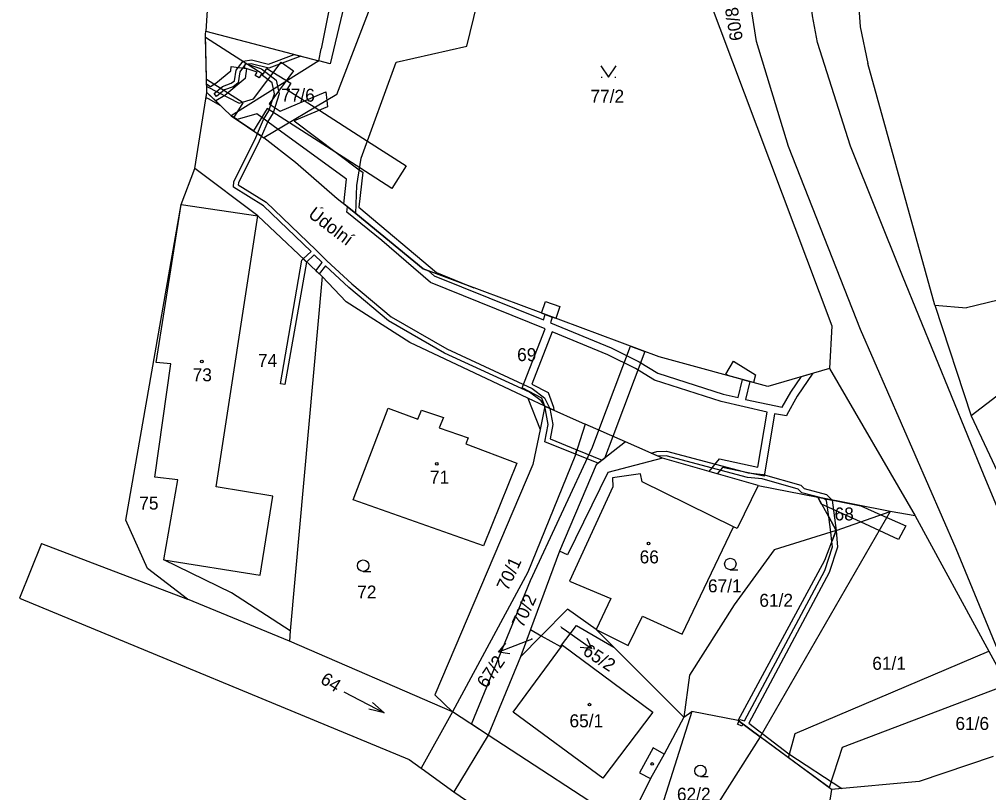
# Model space of a CAD drawing. Extents: x -670359 to -668019, y -978807 to -976674.
# Drawn here: x -670358.7 to -670231.4, y -977812.9 to -977711.4 of the extents above; entities that cross this region are included whole.
import ezdxf

# ---------------------------------------------------------------- set-up
doc = ezdxf.new("R2010")
doc.units = 0
for name, color, linetype in [('Hranice kat_území', 7, 'Continuous'), ('Hranice parcel', 7, 'Continuous'), ('Parcelní čísla', 7, 'Continuous'), ('Pop  PČ popisy', 7, 'Continuous'), ('Vnitřní kresba', 7, 'Continuous'), ('Věcná břemena k části', 7, 'Continuous'), ('Značky budov', 7, 'Continuous'), ('Značky kultur', 7, 'Continuous')]:
    doc.layers.add(name, color=color, linetype=linetype)

msp = doc.modelspace()

# ---------------------------------------------------------------- linework, layer by layer
at = {"layer": 'Hranice kat_území'}
for points in [[(-670332.34, -977684.03), (-670334.21, -977712.94)], [(-670334.24, -977713.37), (-670334.21, -977712.94)], [(-670334.05, -977720.97), (-670334.24, -977713.37)], [(-670335.64, -977730.96), (-670334.05, -977720.97)], [(-670337.44, -977735.66), (-670335.64, -977730.96)], [(-670344.7, -977777.12), (-670337.44, -977735.66)], [(-670341.86, -977783.46), (-670344.7, -977777.12)], [(-670355.76, -977780.18), (-670358.68, -977787.38)], [(-670355.76, -977780.18), (-670336.61, -977787.5)], [(-670336.61, -977787.5), (-670341.86, -977783.46)], [(-670358.68, -977787.38), (-670307.5, -977808.55)], [(-670307.5, -977808.55), (-670305.92, -977809.69)], [(-670305.92, -977809.69), (-670305.49, -977810)], [(-670305.49, -977810), (-670301.94, -977812.57)], [(-670301.94, -977812.57), (-670301.61, -977812.81)], [(-670301.61, -977812.81), (-670283.75, -977825.01)]]:
    msp.add_lwpolyline(points, dxfattribs=at)
at = {"layer": 'Hranice parcel'}
for points in [[(-670228.39, -977798.54), (-670235.68, -977780.88), (-670248.21, -977752.09), (-670257.66, -977728.06), (-670261.88, -977714.27), (-670262.87, -977707.81), (-670263.3, -977700.83), (-670262.9, -977694.87), (-670261.36, -977686.41), (-670250.36, -977641.2)], [(-670183.39, -977889.81), (-670193.56, -977862.25), (-670201.26, -977845.22), (-670205.62, -977834.5), (-670231.98, -977771.32), (-670242.71, -977745.05), (-670249.53, -977728.04), (-670253.85, -977714.41), (-670254.54, -977710.9), (-670255.07, -977705.75), (-670255.17, -977699.87), (-670254.7, -977694.67), (-670252.82, -977684.15), (-670242.83, -977643.13)], [(-670306.8, -977670.72), (-670317.87, -977717.22)], [(-670299.92, -977714.89), (-670294.49, -977692.62)], [(-670248.85, -977704.32), (-670248.28, -977712.37)], [(-670317.01, -977721.25), (-670311.54, -977706.97)], [(-670268.34, -977708.07), (-670252.01, -977751.62)], [(-670334.21, -977712.94), (-670319.36, -977716.83)], [(-670248.28, -977712.37), (-670247.28, -977717.18)], [(-670309.21, -977716.99), (-670299.92, -977714.89)], [(-670317.87, -977717.22), (-670319.36, -977716.83)], [(-670313.79, -977729.59), (-670309.21, -977716.99)], [(-670238.46, -977748.91), (-670247.28, -977717.18)], [(-670330.87, -977724.03), (-670334.05, -977720.97)], [(-670317.01, -977721.25), (-670326.57, -977726.94)], [(-670330.87, -977724.03), (-670326.57, -977726.94)], [(-670322.43, -977730.17), (-670326.57, -977726.94)], [(-670314.37, -977733.19), (-670313.79, -977729.59)], [(-670327.36, -977737.17), (-670335.64, -977730.96)], [(-670316.95, -977734.93), (-670322.43, -977730.17)], [(-670314.48, -977736.86), (-670314.37, -977733.19)], [(-670314.48, -977736.86), (-670316.95, -977734.93)], [(-670340.71, -977756.44), (-670337.44, -977735.66)], [(-670332.82, -977772.73), (-670327.36, -977737.17)], [(-670318.94, -977745.15), (-670327.36, -977737.17)], [(-670305.65, -977744.12), (-670314.48, -977736.86)], [(-670318.94, -977745.15), (-670323.11, -977791.67)], [(-670315.76, -977748.45), (-670318.94, -977745.15)], [(-670274.68, -977755.7), (-670305.65, -977744.12)], [(-670227.25, -977747.55), (-670234.3, -977749.26)], [(-670307.4, -977753.79), (-670315.76, -977748.45)], [(-670238.46, -977748.91), (-670233.69, -977763.42)], [(-670238.46, -977748.91), (-670234.3, -977749.26)], [(-670252.01, -977751.62), (-670252.29, -977757.21)], [(-670291.93, -977761.1), (-670307.4, -977753.79)], [(-670220.97, -977753.67), (-670233.69, -977763.42)], [(-670340.89, -977771.47), (-670338.79, -977756.61)], [(-670338.79, -977756.61), (-670340.71, -977756.44)], [(-670260.39, -977759.56), (-670274.68, -977755.7)], [(-670252.29, -977757.21), (-670260.39, -977759.56)], [(-670252.29, -977757.21), (-670241.06, -977776.57)], [(-670289.68, -977762.16), (-670291.93, -977761.1)], [(-670314.83, -977774.45), (-670310.26, -977762.41)], [(-670310.26, -977762.41), (-670306.35, -977763.87)], [(-670306.35, -977763.87), (-670305.86, -977762.68)], [(-670305.86, -977762.68), (-670302.99, -977763.66)], [(-670289.68, -977762.16), (-670290.31, -977765.22)], [(-670289.68, -977762.16), (-670284.38, -977764.51)], [(-670302.99, -977763.66), (-670303.56, -977765.01)], [(-670233.69, -977763.42), (-670224.46, -977783.08)], [(-670303.56, -977765.01), (-670299.73, -977766.32)], [(-670290.31, -977765.22), (-670291.27, -977769.82)], [(-670284.38, -977764.51), (-670285.74, -977768.77)], [(-670279.08, -977766.86), (-670284.38, -977764.51)], [(-670299.73, -977766.32), (-670300.05, -977767.12)], [(-670279.08, -977766.86), (-670282.95, -977769.88)], [(-670274.22, -977768.98), (-670279.08, -977766.86)], [(-670300.05, -977767.12), (-670293.35, -977769.64)], [(-670285.74, -977768.77), (-670291.91, -977783.94)], [(-670261.68, -977772.58), (-670274.22, -977768.98)], [(-670291.27, -977769.82), (-670304.13, -977800.04)], [(-670293.35, -977769.64), (-670297.75, -977780.49)], [(-670282.95, -977769.88), (-670287.75, -977781.2)], [(-670337.86, -977771.81), (-670340.89, -977771.47)], [(-670339.7, -977782.35), (-670337.86, -977771.81)], [(-670277.11, -977771.04), (-670280.8, -977771.57)], [(-670280.8, -977771.57), (-670280.73, -977772.77)], [(-670276.88, -977772.08), (-670277.11, -977771.04)], [(-670264.92, -977778), (-670276.88, -977772.08)], [(-670325.39, -977773.98), (-670332.82, -977772.73)], [(-670280.73, -977772.77), (-670286.42, -977785.13)], [(-670261.68, -977772.58), (-670253.83, -977774.12)], [(-670327.06, -977784.36), (-670325.39, -977773.98)], [(-670297.75, -977780.49), (-670314.83, -977774.45)], [(-670244.34, -977775.98), (-670253.83, -977774.12)], [(-670253.83, -977774.12), (-670251.4, -977778.49)], [(-670251.4, -977778.49), (-670244.34, -977775.98)], [(-670241.06, -977776.57), (-670244.34, -977775.98)], [(-670241.06, -977776.57), (-670231.37, -977794.32), (-670228.95, -977798.75), (-670226.38, -977803.45)], [(-670271.66, -977792.11), (-670264.92, -977778)], [(-670251.4, -977778.49), (-670259.58, -977781)], [(-670252.93, -977782.4), (-670251.4, -977778.49)], [(-670287.75, -977781.2), (-670291.56, -977791.5)], [(-670259.58, -977781), (-670264.83, -977788.24)], [(-670330.84, -977786.66), (-670339.7, -977782.35)], [(-670339.7, -977782.35), (-670327.06, -977784.36)], [(-670264.3, -977803.44), (-670252.93, -977782.4)], [(-670291.91, -977783.94), (-670301.8, -977802.31)], [(-670286.42, -977785.13), (-670280.99, -977787.4)], [(-670323.11, -977791.67), (-670330.84, -977786.66)], [(-670323.2, -977793.03), (-670336.61, -977787.5)], [(-670280.99, -977787.4), (-670282.94, -977791.47)], [(-670264.83, -977788.24), (-670270.66, -977797.47)], [(-670286.68, -977788.8), (-670290.14, -977792.3)], [(-670282.94, -977791.47), (-670286.68, -977788.8)], [(-670278.72, -977793.58), (-670276.85, -977789.75)], [(-670276.85, -977789.75), (-670271.66, -977792.11)], [(-670287.6, -977793.72), (-670285.54, -977790.94)], [(-670285.54, -977790.94), (-670280.61, -977793.8)], [(-670323.11, -977791.67), (-670323.2, -977793.03)], [(-670291.56, -977791.5), (-670292.89, -977795.08)], [(-670290.14, -977792.3), (-670292.89, -977795.08)], [(-670291.56, -977791.5), (-670290.14, -977792.3)], [(-670290.14, -977792.3), (-670287.6, -977793.72)], [(-670282.94, -977791.47), (-670278.72, -977793.58)], [(-670280.61, -977793.8), (-670282.94, -977791.47)], [(-670301.8, -977802.31), (-670323.2, -977793.03)], [(-670271.42, -977802.99), (-670280.61, -977793.8)], [(-670292.89, -977795.08), (-670297.12, -977805.37)], [(-670270.66, -977797.47), (-670271.42, -977802.99)], [(-670304.13, -977800.04), (-670301.8, -977802.31)], [(-670297.12, -977805.37), (-670301.8, -977802.31)], [(-670270.38, -977802.27), (-670276.02, -977820.05)], [(-670271.42, -977802.99), (-670270.38, -977802.27)], [(-670264.3, -977803.44), (-670270.38, -977802.27)], [(-670271.42, -977802.99), (-670274.02, -977807.85)], [(-670264.3, -977803.44), (-670261.39, -977805.59)], [(-670278.88, -977817.26), (-670297.12, -977805.37)], [(-670261.39, -977805.59), (-670272.64, -977823.3)], [(-670252.04, -977812.48), (-670261.39, -977805.59)], [(-670274.02, -977807.85), (-670275.8, -977811.03)], [(-670230.81, -977808.15), (-670240.51, -977811.44)], [(-670275.8, -977811.03), (-670278.88, -977817.26)], [(-670240.51, -977811.44), (-670252.04, -977812.48)], [(-670252.04, -977812.48), (-670254.6, -977829.13)]]:
    msp.add_lwpolyline(points, dxfattribs=at)
at = {"layer": 'Parcelní čísla'}
for p, q in [((-670287.52, -977791.17), (-670286.82, -977791.67)), ((-670291.36, -977792.76), (-670292.03, -977793.02)), ((-670284.18, -977792.62), (-670283.56, -977793.99)), ((-670294.29, -977794.68), (-670295.77, -977794.45))]:
    msp.add_line(p, q, dxfattribs=at)
for points in [[(-670286.82, -977791.67), (-670283.56, -977793.99), (-670285.05, -977793.85)], [(-670292.03, -977793.02), (-670295.77, -977794.45), (-670294.82, -977793.28)]]:
    msp.add_lwpolyline(points, dxfattribs=at)
at = {"layer": 'Vnitřní kresba'}
for points in [[(-670316.89, -977704.46), (-670319.04, -977715.24)], [(-670319.36, -977716.83), (-670319.04, -977715.24)], [(-670319.36, -977716.83), (-670330.87, -977724.03)], [(-670337.44, -977735.66), (-670327.36, -977737.17)], [(-670291.93, -977761.1), (-670290.31, -977765.22)], [(-670274.22, -977768.98), (-670281.39, -977770.85)], [(-670281.39, -977770.85), (-670286.71, -977781.69)], [(-670261.68, -977772.58), (-670264.44, -977778.24)], [(-670264.44, -977778.24), (-670264.92, -977778)], [(-670286.71, -977781.69), (-670287.75, -977781.2)], [(-670293.82, -977802.35), (-670287.36, -977793.52)], [(-670287.36, -977793.52), (-670275.5, -977802.32)], [(-670301.8, -977802.31), (-670305.92, -977809.69)], [(-670282.04, -977810.99), (-670293.82, -977802.35)], [(-670275.5, -977802.32), (-670282.04, -977810.99)], [(-670297.12, -977805.37), (-670301.61, -977812.81)], [(-670275.45, -977807.04), (-670277.23, -977810.3)], [(-670274.02, -977807.85), (-670275.45, -977807.04)], [(-670277.23, -977810.3), (-670275.8, -977811.03)]]:
    msp.add_lwpolyline(points, dxfattribs=at)
at = {"layer": 'Věcná břemena k části'}
for p, q in [((-670334.23, -977713.7), (-670326.68, -977718.55)), ((-670334.09, -977719.27), (-670334.23, -977713.7)), ((-670325.98, -977717.24), (-670322.58, -977715.99)), ((-670330.21, -977718.04), (-670329.3, -977716.86)), ((-670329.02, -977717.32), (-670329.73, -977718.24)), ((-670329.3, -977716.86), (-670328.22, -977716.7)), ((-670328.24, -977717.2), (-670329.02, -977717.32)), ((-670325.94, -977717.76), (-670328.24, -977717.2)), ((-670328.22, -977716.7), (-670325.98, -977717.24)), ((-670321.73, -977716.21), (-670325.94, -977717.76)), ((-670330.42, -977719.43), (-670330.21, -977718.04)), ((-670329.73, -977718.24), (-670329.96, -977719.69)), ((-670326.68, -977718.55), (-670326.18, -977717.83)), ((-670326.18, -977717.83), (-670323.04, -977719.73)), ((-670329.3, -977722.32), (-670334.09, -977719.27)), ((-670332.02, -977720.19), (-670330.85, -977719.77)), ((-670330.85, -977719.77), (-670330.42, -977719.43)), ((-670329.96, -977719.69), (-670330.61, -977720.21)), ((-670323.04, -977719.73), (-670323.55, -977720.56)), ((-670333.11, -977721.11), (-670332.02, -977720.19)), ((-670332.79, -977721.49), (-670333.11, -977721.11)), ((-670331.76, -977720.63), (-670332.79, -977721.49)), ((-670330.61, -977720.21), (-670331.76, -977720.63)), ((-670323.55, -977720.56), (-670319.85, -977722.94)), ((-670330.5, -977724.28), (-670329.3, -977722.32)), ((-670326.14, -977723.06), (-670327.94, -977726.01)), ((-670323.21, -977724.94), (-670326.14, -977723.06)), ((-670319.85, -977722.94), (-670312.98, -977727.35)), ((-670327.94, -977726.01), (-670330.5, -977724.28)), ((-670313.99, -977730.85), (-670323.21, -977724.94)), ((-670312.98, -977727.35), (-670307.88, -977730.62)), ((-670309.78, -977733.56), (-670313.99, -977730.85)), ((-670307.88, -977730.62), (-670309.78, -977733.56))]:
    msp.add_line(p, q, dxfattribs=at)
for points in [[(-670322.58, -977715.99), (-670321.73, -977716.21)], [(-670334.05, -977720.97), (-670334.06, -977720.64), (-670334.07, -977720.17), (-670329.81, -977722.37), (-670327.92, -977721.8), (-670324.3, -977716.98), (-670322.67, -977718.13), (-670325.87, -977722.47), (-670324.45, -977723.44), (-670318.42, -977720.87), (-670318.32, -977722.03), (-670318.24, -977722.87), (-670322.58, -977724.7), (-670314.04, -977731.12), (-670313.6, -977731.45), (-670314.11, -977736.04), (-670303.92, -977744.63), (-670299, -977746.61), (-670305.65, -977744.12), (-670314.48, -977736.86), (-670316.08, -977735.61), (-670315.71, -977732.34), (-670324.69, -977725.82), (-670327.52, -977723.76), (-670330.06, -977724.53), (-670330.87, -977724.03), (-670334.05, -977720.97)], [(-670329.16, -977717.75), (-670328.97, -977717.18), (-670326.87, -977717.87), (-670324.94, -977719.36), (-670324.56, -977721.17), (-670325.37, -977723.64), (-670326.07, -977724.78), (-670326.9, -977726.72), (-670327.41, -977726.37), (-670326.61, -977724.5), (-670325.91, -977723.38), (-670325.18, -977721.13), (-670325.48, -977719.7), (-670326.92, -977718.59), (-670327.18, -977719.03), (-670327.7, -977718.73), (-670327.46, -977718.31), (-670329.16, -977717.75)], [(-670334.08, -977719.87), (-670333.59, -977720.18), (-670332.87, -977719.75), (-670330.92, -977718.11), (-670330.85, -977717.58), (-670328.86, -977717.84), (-670329.03, -977719.14), (-670331.71, -977721.38), (-670332.88, -977722.09), (-670334.05, -977720.97), (-670334.06, -977720.64), (-670334.07, -977720.17), (-670334.08, -977719.87)], [(-670332.23, -977722.72), (-670333.84, -977721.81), (-670334.16, -977721.68), (-670334.05, -977720.97)], [(-670334.05, -977720.97), (-670332.88, -977722.09), (-670332.23, -977722.72)], [(-670327.17, -977727.35), (-670329.92, -977732.83), (-670329.93, -977733.1), (-670326.27, -977735.37), (-670319.73, -977741.64), (-670318.3, -977743.07), (-670315.01, -977746.1), (-670309.86, -977750.45), (-670302.56, -977754.64), (-670291.36, -977759.82), (-670289.72, -977761.08), (-670289, -977762.46), (-670289.68, -977762.16), (-670290.18, -977761.48), (-670291.68, -977760.34), (-670302.84, -977755.18), (-670310.2, -977750.95), (-670315.41, -977746.56), (-670318.48, -977743.73), (-670319.33, -977744.78), (-670319.76, -977744.37), (-670318.91, -977743.31), (-670319.95, -977742.27), (-670320.97, -977743.23), (-670321.4, -977742.82), (-670320.37, -977741.85), (-670326.63, -977735.85), (-670330.55, -977733.42), (-670330.52, -977732.67), (-670327.71, -977727.09), (-670327.41, -977726.37), (-670326.9, -977726.72), (-670327.17, -977727.35)], [(-670289.65, -977751.99), (-670304.71, -977745.92), (-670311.07, -977740.41), (-670315.7, -977736.68), (-670315.61, -977735.98)], [(-670315.61, -977735.98), (-670314.48, -977736.86), (-670305.65, -977744.12), (-670304.97, -977744.37)], [(-670321.4, -977742.82), (-670320.97, -977743.23), (-670323.81, -977759.32), (-670324.4, -977759.21), (-670321.58, -977742.99), (-670321.4, -977742.82)], [(-670304.97, -977744.37), (-670304.19, -977745.05), (-670289.87, -977750.82), (-670289.63, -977750.11)], [(-670290.1, -977749.94), (-670289.58, -977748.42), (-670287.69, -977749.06), (-670288.22, -977750.64), (-670290.1, -977749.94)], [(-670289.63, -977750.11), (-670288.7, -977750.46)], [(-670288.7, -977750.46), (-670288.95, -977751.22), (-670280.98, -977754.49), (-670277.29, -977756.35), (-670274.84, -977757.81), (-670266.25, -977760.59), (-670264.3, -977761.04), (-670263.72, -977758.66)], [(-670289.68, -977762.16), (-670290.06, -977761.09), (-670292.65, -977759.76), (-670289.65, -977751.99)], [(-670254.47, -977757.84), (-670256.52, -977760.85), (-670257.9, -977763.31), (-670257.96, -977763.42), (-670259.51, -977763.15), (-670260.88, -977771.37), (-670266.35, -977770.2), (-670267.04, -977771.04), (-670268.08, -977770.74), (-670266.74, -977769.09), (-670261.69, -977770.18), (-670260.49, -977762.95), (-670266.52, -977761.55), (-670275.26, -977758.73), (-670277.77, -977757.23), (-670281.4, -977755.4), (-670288.73, -977752.4), (-670291.39, -977759.28), (-670289.26, -977760.38), (-670288.54, -977762.31), (-670288.48, -977762.69)], [(-670278.43, -977754.3), (-670276.55, -977755), (-670280.76, -977766.12), (-670281.86, -977769.03), (-670282.95, -977769.88), (-670287.75, -977781.2), (-670291.56, -977791.5), (-670292.89, -977795.08), (-670297.12, -977805.37), (-670299.33, -977803.92), (-670291.55, -977785.06), (-670283.43, -977767.52), (-670282.59, -977765.3), (-670278.43, -977754.3)], [(-670265.65, -977758.14), (-670265.93, -977757.96), (-670264.89, -977756.26), (-670262.01, -977758.03), (-670262.27, -977759.05), (-670265.65, -977758.14)], [(-670255.98, -977758.28), (-670254.47, -977757.84)], [(-670263.72, -977758.66), (-670262.75, -977758.92)], [(-670262.75, -977758.92), (-670263.33, -977761.27), (-670258.51, -977762.31), (-670257.37, -977760.33), (-670255.98, -977758.28)], [(-670289.68, -977762.16), (-670289, -977762.46), (-670288.62, -977764.57), (-670288.99, -977766.46), (-670285.46, -977767.89), (-670285.64, -977768.46), (-670289.67, -977766.84), (-670289.24, -977764.57), (-670289.68, -977762.16)], [(-670288.48, -977762.69), (-670289.68, -977762.16)], [(-670285.46, -977767.89), (-670282.13, -977769.24), (-670282.67, -977769.66), (-670285.64, -977768.46), (-670285.46, -977767.89)], [(-670273.69, -977768.06), (-670262.98, -977770.92), (-670261.01, -977771.11), (-670256.07, -977772.52), (-670255.61, -977772.99), (-670252.71, -977773.76), (-670251.96, -977774.49), (-670253.02, -977774.28), (-670255.93, -977773.53), (-670256.39, -977773.06), (-670261.13, -977771.71), (-670263.08, -977771.52), (-670273.75, -977768.66), (-670274.82, -977768.72), (-670275.71, -977768.33), (-670274.96, -977768.13), (-670273.69, -977768.06)], [(-670253.83, -977774.12), (-670248.17, -977775.23), (-670245.55, -977776.41), (-670242.28, -977777.89), (-670243.23, -977779.65), (-670248.22, -977777.36), (-670253.34, -977775.01), (-670253.83, -977774.12)], [(-670252.4, -977776.7), (-670252.68, -977774.54), (-670253.02, -977774.28), (-670251.96, -977774.49), (-670251.4, -977778.49), (-670252.4, -977776.7)], [(-670244.34, -977775.98), (-670261.39, -977805.59), (-670264.3, -977803.44), (-670252.93, -977782.4), (-670251.4, -977778.49), (-670244.34, -977775.98)], [(-670252.4, -977776.7), (-670251.4, -977778.49), (-670251.97, -977779.94), (-670252.13, -977778.71), (-670252.4, -977776.7)], [(-670251.97, -977779.94), (-670251.4, -977778.49), (-670251.26, -977780.68), (-670252.33, -977783.99), (-670262.91, -977803.76), (-670257.65, -977807.8), (-670250.67, -977812.36), (-670252.04, -977812.48), (-670263.67, -977803.91), (-670264.18, -977803.53), (-670264.07, -977803.32), (-670263.44, -977803.49), (-670252.89, -977783.75), (-670251.88, -977780.62), (-670251.97, -977779.94)], [(-670257.67, -977808.33), (-670256.79, -977805.13), (-670231.37, -977794.32)], [(-670231.37, -977794.32), (-670228.95, -977798.75), (-670250.62, -977806.97)], [(-670264.18, -977803.53), (-670263.67, -977803.91), (-670263.81, -977804.18), (-670264.37, -977803.91), (-670264.18, -977803.53)], [(-670250.62, -977806.97), (-670252.36, -977812.24), (-670257.67, -977808.33)]]:
    msp.add_lwpolyline(points, dxfattribs=at)
at = {"layer": 'Značky budov'}
for centre in [(-670334.72, -977756.29), (-670303.88, -977769.73), (-670276.05, -977780.2), (-670283.8, -977801.35)]:
    msp.add_circle(centre, 0.175, dxfattribs=at)
at = {"layer": 'Značky kultur'}
for p, q in [((-670282.27, -977718.96), (-670282.17, -977718.96)), ((-670280.47, -977718.96), (-670280.37, -977718.96)), ((-670313.53, -977783.85), (-670312.53, -977783.85)), ((-670265.32, -977783.63), (-670264.32, -977783.63)), ((-670316.09, -977799.66), (-670310.77, -977802.42)), ((-670269.25, -977810.79), (-670268.25, -977810.79))]:
    msp.add_line(p, q, dxfattribs=at)
for points in [[(-670282.32, -977717.46), (-670281.32, -977718.96), (-670280.32, -977717.46)], [(-670312.31, -977801.06), (-670310.77, -977802.42), (-670312.77, -977801.94)]]:
    msp.add_lwpolyline(points, dxfattribs=at)
for centre, radius in [((-670334.72, -977756.29), 0.175), ((-670303.88, -977769.73), 0.175), ((-670276.05, -977780.2), 0.175), ((-670265.32, -977782.88), 0.75), ((-670313.53, -977783.1), 0.75), ((-670283.8, -977801.35), 0.175), ((-670275.58, -977809.14), 0.175), ((-670269.25, -977810.04), 0.75)]:
    msp.add_circle(centre, radius, dxfattribs=at)

# ---------------------------------------------------------------- texts
at = {"layer": 'Parcelní čísla'}
for s, rotation, p in [('60/8', 99.1577, (-670263.65, -977714.04)), ('70/1', 65.1858, (-670294.55, -977786.52)), ('70/2', 65.4401, (-670292.55, -977791.37)), ('65/2', 326.616, (-670284.83, -977794.67)), ('67/2', 55.1271, (-670297.35, -977799.31)), ('64', 327.6671, (-670319.29, -977798.43))]:
    msp.add_text(s, height=1.7, rotation=rotation, dxfattribs=at).set_placement(p)
for s, height, p in [('77/6', 1.7, (-670324.31, -977722.18)), ('77/2', 1.7, (-670283.69, -977722.32)), ('74', 1.7, (-670327.35, -977757)), ('69', 1.7, (-670293.32, -977756.24)), ('73', 1.7, (-670335.93, -977758.89)), ('71', 1.7, (-670304.77, -977772.33)), ('75', 1.7, (-670342.94, -977775.74)), ('68', 1.7, (-670251.63, -977777.16)), ('66', 1.7, (-670277.23, -977782.8)), ('67/1', 1.7, (-670268.26, -977786.6)), ('72', 1.7, (-670314.32, -977787.41)), ('61/2', 1.7, (-670261.51, -977788.5)), ('65/2', 0.1, (-670287.68, -977791.17)), ('67/2', 0.1, (-670291.52, -977792.76)), ('61/1', 1.7, (-670246.68, -977796.77)), ('65/1', 1.7, (-670286.44, -977804.32)), ('61/6', 1.7, (-670235.76, -977804.67)), ('62/2', 1.7, (-670272.33, -977813.95))]:
    msp.add_text(s, height=height, dxfattribs=at).set_placement(p)
at = {"layer": 'Pop  PČ popisy'}
msp.add_text('Údolní', height=1.7, rotation=322.8528, dxfattribs=at).set_placement((-670320.87, -977737.22))

doc.saveas('drawing.dxf')
